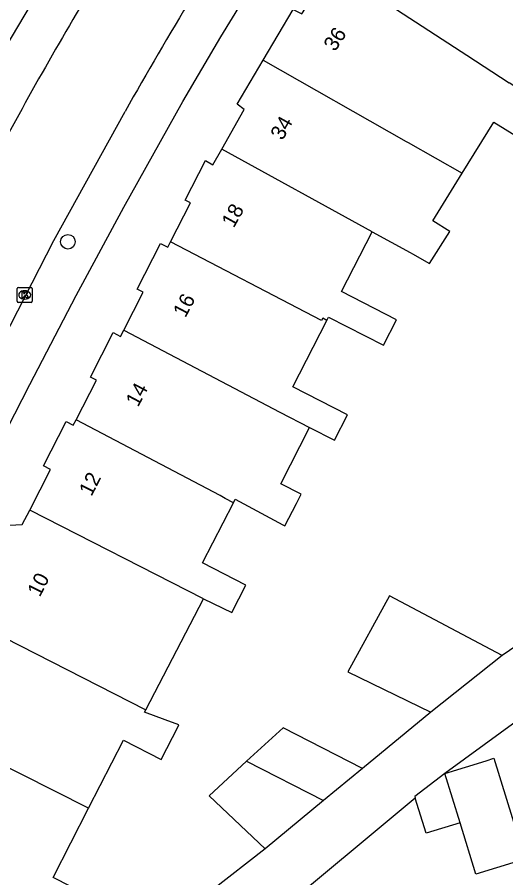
# Model space of a CAD drawing. Extents: x 160356 to 161355, y 381727 to 382845.
# Drawn here: x 161178.6 to 161211.3, y 382396.6 to 382454.3 of the extents above; entities that cross this region are included whole.
import ezdxf

# ---------------------------------------------------------------- set-up
doc = ezdxf.new("R2010")
doc.units = 0
for name, color, linetype in [('IMGEO_Boom', 7, 'Continuous'), ('IMGEO_Kolk', 7, 'Continuous'), ('IMGEO_Pand', 7, 'Continuous'), ('IMGEO_Pand_nummerreeks', 7, 'Continuous'), ('IMGEO_Rijbaan_lokaal_open', 7, 'Continuous'), ('IMGEO_Voetpad_halfverhard', 7, 'Continuous'), ('IMGEO_Voetpad_open', 7, 'Continuous')]:
    doc.layers.add(name, color=color, linetype=linetype)

msp = doc.modelspace()

# ---------------------------------------------------------------- linework, layer by layer
at = {"layer": 'IMGEO_Boom'}
msp.add_circle((161181.959, 382439.224), 0.489, dxfattribs=at)
at = {"layer": 'IMGEO_Kolk'}
for p, q in [((161178.57, 382435.238), (161178.57, 382436.09)), ((161178.645, 382436.164), (161179.497, 382436.164)), ((161179.058, 382435.944), (161179.083, 382435.944)), ((161179.571, 382436.09), (161179.571, 382435.238)), ((161179.497, 382435.164), (161178.645, 382435.164)), ((161179.081, 382435.384), (161179.056, 382435.384))]:
    msp.add_line(p, q, dxfattribs=at)
for points in [[(161178.57, 382435.238), (161178.57, 382436.09)], [(161178.645, 382436.164), (161179.497, 382436.164)], [(161178.891, 382435.864), (161179.014, 382435.864), (161179.014, 382435.713), (161179.144, 382435.864), (161179.308, 382435.864), (161179.162, 382435.713), (161179.315, 382435.464), (161179.163, 382435.464), (161179.078, 382435.628), (161179.014, 382435.561), (161179.014, 382435.464), (161178.891, 382435.464), (161178.891, 382435.864)], [(161179.571, 382436.09), (161179.571, 382435.238)], [(161179.497, 382435.164), (161178.645, 382435.164)]]:
    msp.add_lwpolyline(points, dxfattribs=at)
for centre, start, end in [((161178.647, 382436.088), 91.55205, 178.44795), ((161178.647, 382436.088), 91.55205, 178.44795), ((161179.495, 382436.088), 1.55205, 88.44795), ((161179.495, 382436.088), 1.55205, 88.44795), ((161178.647, 382435.24), 181.55205, 268.44795), ((161178.647, 382435.24), 181.55205, 268.44795), ((161179.495, 382435.24), 271.55205, 358.44795), ((161179.495, 382435.24), 271.55205, 358.44795)]:
    msp.add_arc(centre, 0.0765, start, end, dxfattribs=at)
for centre, major_axis, ratio, start_param, end_param in [((161179.057, 382435.664), (-0.387, 0.002), 0.722429, 4.712389, 7.853982), ((161179.082, 382435.664), (-0.39, 0.002), 0.717154, 1.570796, 4.712389)]:
    msp.add_ellipse(centre, major_axis=major_axis, ratio=ratio, start_param=start_param, end_param=end_param, dxfattribs=at)
at = {"layer": 'IMGEO_Pand'}
for points in [[(161195.029, 382451.387), (161197.036, 382454.795), (161197.607, 382454.506), (161199.627, 382457.63)], [(161199.627, 382457.63), (161208.266, 382451.977), (161208.659, 382451.72), (161211.492, 382449.866)], [(161192.268, 382445.439), (161193.748, 382448.086), (161193.297, 382448.445), (161195.029, 382451.387)], [(161195.029, 382451.387), (161204.591, 382445.954), (161204.733, 382445.873), (161208.346, 382443.82)], [(161208.346, 382443.82), (161210.452, 382447.24), (161213.037, 382445.649), (161214.444, 382447.934), (161211.492, 382449.866)], [(161188.827, 382439.232), (161190.16, 382441.838), (161189.816, 382442.014), (161191.17, 382444.661), (161191.67, 382444.37), (161192.268, 382445.439)], [(161202.323, 382439.895), (161192.268, 382445.439)], [(161202.323, 382439.895), (161204.854, 382438.5), (161205.015, 382438.41), (161206.162, 382437.779), (161207.517, 382439.918), (161206.385, 382440.635), (161208.346, 382443.82)], [(161199.287, 382433.96), (161199.399, 382434.18), (161203.069, 382432.308), (161203.939, 382434.008), (161200.271, 382435.885), (161202.323, 382439.895)], [(161185.702, 382433.303), (161187.002, 382435.843), (161186.597, 382436.05), (161188.163, 382439.111), (161188.64, 382438.867), (161188.827, 382439.232)], [(161199.287, 382433.96), (161199.01, 382434.11), (161198.924, 382433.951), (161188.827, 382439.232)], [(161198.135, 382426.784), (161199.806, 382425.928), (161200.676, 382427.628), (161197.007, 382429.503), (161199.287, 382433.96)], [(161182.51, 382427.305), (161183.871, 382429.965), (161183.473, 382430.168), (161184.992, 382433.138), (161185.488, 382432.884), (161185.702, 382433.303)], [(161185.702, 382433.303), (161196.139, 382427.806), (161198.135, 382426.784)], [(161179.403, 382421.258), (161180.796, 382423.98), (161180.326, 382424.221), (161181.839, 382427.179), (161182.32, 382426.933), (161182.51, 382427.305)], [(161193.04, 382421.748), (161192.489, 382422.039), (161192.143, 382422.222), (161182.51, 382427.305)], [(161193.04, 382421.748), (161193.163, 382421.988), (161196.344, 382420.269), (161196.484, 382420.196), (161197.253, 382421.696), (161197.572, 382422.32), (161196.209, 382423.018), (161198.135, 382426.784)], [(161175.587, 382413.794), (161177.836, 382418.191), (161177.377, 382418.9), (161178.062, 382420.239), (161178.904, 382420.282), (161179.403, 382421.258)], [(161191.038, 382415.306), (161179.403, 382421.258)], [(161191.038, 382415.306), (161192.922, 382414.395), (161193.861, 382416.231), (161190.973, 382417.709), (161193.04, 382421.748)], [(161211.03, 382411.518), (161203.482, 382415.513), (161200.689, 382410.415), (161206.249, 382407.708)], [(161187.173, 382407.865), (161191.038, 382415.306)], [(161175.587, 382413.794), (161187.173, 382407.865)], [(161211.03, 382411.518), (161206.249, 382407.708)], [(161183.346, 382401.295), (161185.675, 382405.848), (161188.202, 382404.555), (161189.331, 382406.762), (161189.383, 382406.863), (161188.473, 382407.2), (161187.093, 382407.711), (161187.173, 382407.865)], [(161183.346, 382401.295), (161172.088, 382406.955)], [(161201.665, 382403.951), (161196.357, 382406.672), (161193.918, 382404.428)], [(161207.177, 382403.61), (161209.94, 382404.466), (161210.462, 382404.628), (161212.544, 382397.909), (161212.031, 382397.716), (161209.268, 382396.86), (161208.2, 382400.309)], [(161193.918, 382404.428), (161191.411, 382402.121), (161195.15, 382398.567)], [(161193.918, 382404.428), (161199.07, 382401.806)], [(161201.665, 382403.951), (161199.07, 382401.806)], [(161207.177, 382403.61), (161205.177, 382402.062), (161205.207, 382401.964)], [(161208.2, 382400.309), (161207.177, 382403.61)], [(161199.07, 382401.806), (161195.15, 382398.567)], [(161208.2, 382400.309), (161205.937, 382399.608), (161205.207, 382401.964)], [(161188.07, 382393.017), (161180.97, 382396.649), (161183.346, 382401.295)]]:
    msp.add_lwpolyline(points, dxfattribs=at)
at = {"layer": 'IMGEO_Rijbaan_lokaal_open'}
msp.add_lwpolyline([(161175.683, 382428.919), (161181.009, 382439.313), (161185.786, 382447.958)], dxfattribs=at)
for centre, radius, start, end in [((161461.414, 382292.316), 316.536, 147.31894, 150.54748), ((161389.843, 382332.127), 240.745, 148.7932, 152.28401)]:
    msp.add_arc(centre, radius, start, end, dxfattribs=at)
at = {"layer": 'IMGEO_Voetpad_halfverhard'}
for points in [[(161229.212, 382420.525), (161228.573, 382419.971), (161223.953, 382416.426), (161213.527, 382408.229), (161207.177, 382403.61)], [(161217.876, 382416.359), (161215.92, 382414.869), (161211.03, 382411.518)], [(161206.249, 382407.708), (161201.665, 382403.951)], [(161205.207, 382401.964), (161195.594, 382393.934)], [(161195.15, 382398.567), (161188.07, 382393.017)]]:
    msp.add_lwpolyline(points, dxfattribs=at)
at = {"layer": 'IMGEO_Voetpad_open'}
for points in [[(161158.773, 382389.678), (161173.417, 382418.063), (161176.353, 382423.736), (161179.413, 382429.66), (161182.517, 382435.623), (161185.705, 382441.548), (161189.65, 382448.632), (161192.202, 382452.95), (161196.159, 382459.448), (161200.028, 382465.315), (161203.847, 382471.179), (161204.735, 382472.289), (161210.047, 382479.381), (161217.079, 382488.697)], [(161181.334, 382458.271), (161176.806, 382450.653), (161172.789, 382443), (161171.359, 382440.223), (161168.609, 382434.914), (161165.522, 382428.911), (161164.374, 382426.647), (161153.316, 382405.165)]]:
    msp.add_lwpolyline(points, dxfattribs=at)

# ---------------------------------------------------------------- texts
at = {"layer": 'IMGEO_Pand_nummerreeks'}
for s, rotation, p in [('36', 57.11243, (161199.839, 382451.917)), ('34', 60.78509, (161196.323, 382445.97)), ('18', 60.99709, (161193.061, 382440.106)), ('16', 62.21176, (161189.823, 382434.088)), ('14', 61.97684, (161186.656, 382428.113)), ('12', 62.80763, (161183.537, 382422.125)), ('10', 62.91596, (161180.082, 382415.381))]:
    msp.add_text(s, height=1, rotation=rotation, dxfattribs=at).set_placement(p)

doc.saveas('drawing.dxf')
